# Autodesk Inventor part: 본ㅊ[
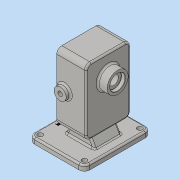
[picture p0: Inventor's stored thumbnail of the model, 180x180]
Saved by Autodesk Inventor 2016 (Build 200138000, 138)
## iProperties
Created: 2020-04
Part Number: 본ㅊ[
Material: 일반
Document SubType Name: Modeling
Designer: Administrator
Density: 1 g/cm^3
Appearance: 기본값
Author: Administrator
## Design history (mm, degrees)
sketch "스케치1"
  geometry: L1 (50, 60)-(-50, 60); L2 (-50, 60)-(-50, -60); L3 (-50, -60)-(50, -60); L4 (50, -60)-(50, 60); L5 (50, 60)-(-50, -60); L6 (-50, 60)-(50, -60); 1 further point
  constraints: 12 end point, 2 midpoint, 2 parallel, 1 horizontal, 1 perpendicular
  dimensions: "d0" = 100 distance of L3.end L2.end; "d1" = 120 distance of L2.end L1.end
extrude "돌출1" new body sketch "스케치1" distance "d2" = 10; taper "d3" = 0 deg
fillet "모깎기1" dims "d4" = 10
fillet "모깎기2" dims "d5" = 3
node "작업 평면1"
sketch "스케치2"
  geometry: L1 (90, 0)-(73, 0); L2 (0, 0)-(80, 0) reference; 1 further point
  constraints: 2 end point, 1 point on line
  dimensions: "d7" = 17 distance of L1.start L1.end
node "작업 평면2"
sketch "스케치3"
  geometry: L1 (0, -60)-(90, -60); L2 (150, -20)-(30, -20); L3 (30, -20)-(30, -100); L4 (30, -100)-(150, -100); L5 (150, -100)-(150, -20); L6 (150, -20)-(30, -100); L7 (30, -20)-(150, -100)
  constraints: 14 end point, 2 horizontal, 2 midpoint, 2 parallel, 1 perpendicular
  dimensions: "d8" = 90 distance of L1.start L1.end; "d9" = 120 distance of L4.end L3.end; "d10" = 80 distance of L3.end L2.end
extrude "돌출2" join sketch "스케치3" distance "d11" = 53; taper "d12" = 0 deg
fillet "모깎기3" dims "d13" = 9
fillet "모깎기4" dims "d14" = 9
sketch "스케치4"
  geometry: L1 (-36, 112)-(-36, 68); L2 (-84, 112)-(-84, 68); A1 r 24 centre (-60, 112) between (-36, 112) and (-84, 112); A2 r 24 centre (-60, 68) between (-84, 68) and (-36, 68); 1 further point
  constraints: 4 end point, 4 point on circle, 2 centre point, 2 tangent, 1 vertical
extrude "돌출3" cut sketch "스케치4" distance "d20" = 29; taper "d21" = 0 deg
sketch "스케치5"
  geometry: C1 r 12.5 at (-60, 112); C2 r 12.5 at (-60, 68); A1 r 24 centre (-60, 112) between (-36, 112) and (-84, 112) reference; A2 r 24 centre (-60, 68) between (-84, 68) and (-36, 68) reference; 1 further point
  constraints: 2 centre point, 2 coincident
  dimensions: "d22" = 25 diameter of C1; "d23" = 25 diameter of C2
extrude "돌출4" cut sketch "스케치5" distance "d24" = 15; taper "d25" = 0 deg
sketch "스케치6"
  geometry: C1 r 12.5 at (60, 112) reference; C2 r 19 at (60, 112); 1 further point
  constraints: 1 centre point, 1 coincident
  dimensions: "d26" = 38 diameter of C2
extrude "돌출5" join sketch "스케치6" distance "d27" = 17; taper "d28" = 0 deg
sketch "스케치7"
  geometry: C1 r 8.5 at (0, 0); 1 further point
  constraints: 1 centre point
  dimensions: "d29" = 17 diameter of C1
extrude "돌출6" cut sketch "스케치7" stored distance "d30" = 17; taper "d31" = 0 deg
fillet "모깎기5" dims "d32" = 3
fillet "모깎기6" dims "d33" = 3
sketch "스케치8"
  geometry: C1 r 14 at (0, 0); 1 further point
  constraints: 1 centre point
  dimensions: "d34" = 28 diameter of C1
extrude "돌출7" cut sketch "스케치8" distance "d35" = 7.3; taper "d36" = 0 deg
chamfer "모따기1" distance "d37" = 0.7; stored, may be unused: second distance "d38" = 2, angle "d39" = 30 deg
feature "분할1"
fillet "모깎기7" dims "d40" = 0.5
chamfer "모따기2" distance "d41" = 1; stored, may be unused: second distance "d42" = 2, angle "d43" = 30 deg
feature "분할2"
sketch "스케치9"
  geometry: L1 (0, 29)-(0, 73) reference; L2 (0, 51)-(-14, 51); C1 r 11 at (-14, 51); 1 further point
  constraints: 2 end point, 1 centre point, 1 coincident, 1 horizontal, 1 midpoint
  dimensions: "d45" = 14 distance of L2.start L2.end; "d46" = 22 diameter of C1
extrude "돌출8" join sketch "스케치9" distance "d47" = 8; taper "d48" = 0 deg
fillet "모깎기8" dims "d49" = 3
hole "구멍1" diameter "d52" = 8.376; stored, may be unused: countersink angle "d56" = 90 deg, drill point angle "d58" = 118 deg; dims "d50" = 10, "d51" = 10, "d53" = 20, "d54" = 4, "d55" = 2, "d57" = 27.3
sketch "스케치10"
  geometry: L1 (-47, 0)-(47, 0) reference; L2 (47, 0)-(47, 50) reference; L3 (-40, 57)-(40, 57) reference; L4 (-47, 0)-(-47, 50) reference; A1 r 7 centre (40, 50) between (47, 50) and (40, 57) reference; A2 r 7 centre (-40, 50) between (-40, 57) and (-47, 50) reference; 1 further point
hole "구멍2" sketch "스케치10" at (40, 50), (-40, 50) diameter "d59" = 9; stored, may be unused: countersink angle "d63" = 90 deg, drill point angle "d65" = 118 deg; dims "d60" = 20, "d61" = 4, "d62" = 2, "d64" = 27.3
sketch "스케치11"
  geometry: L1 (50, -50)-(50, 50) reference; L2 (50, 0)-(33, 0); L3 (33, 0)-(6.5, 0); L4 (-20, -24)-(33, -24); L5 (33, -24)-(33, 24); L6 (33, 24)-(-20, 24); L7 (-20, 24)-(-20, -24); L8 (-20, -24)-(33, 24); L9 (33, -24)-(-20, 24); 1 further point
  constraints: 16 end point, 3 horizontal, 3 midpoint, 2 parallel, 1 perpendicular
  dimensions: "d66" = 17 distance of L2.start L2.end; "d68" = 26.5 distance of L2.end L3.end; "d69" = 53 distance of L6.end L5.end; "d70" = 48 distance of L5.end L4.end
extrude "돌출9" join sketch "스케치11" stored distance "d71" = 8; taper "d72" = -30 deg
feature "면 기울기1" dims angle "d73" = -30 deg
feature "면 기울기2" dims angle "d74" = -30 deg
fillet "모깎기9" dims "d75" = 3
fillet "모깎기10" dims "d76" = 3
sketch "스케치12"
  geometry: L1 (-29, 147)-(-91, 147) reference; L2 (-29, 150)-(-91, 150) reference; L3 (-100, 141)-(-100, 90) reference; L4 (-100, 90)-(-100, 39) reference; L5 (-29, 30)-(-91, 30) reference; L6 (-20, 90)-(-20, 39) reference; L7 (-20, 141)-(-20, 90) reference; L8 (-36, 68)-(-36, 112) reference; L9 (-84, 68)-(-84, 112) reference; A1 r 9 centre (-91, 141) between (-91, 150) and (-100, 141) reference; A2 r 9 centre (-91, 39) between (-100, 39) and (-91, 30) reference; A3 r 9 centre (-29, 39) between (-29, 30) and (-20, 39) reference; A4 r 9 centre (-29, 141) between (-20, 141) and (-29, 150) reference; A5 r 24 centre (-60, 112) between (-36, 112) and (-84, 112) reference; A6 r 24 centre (-60, 68) between (-84, 68) and (-36, 68) reference; 1 further point
hole "구멍3" sketch "스케치12" at (-91, 141) diameter "d77" = 4.134; stored, may be unused: countersink angle "d81" = 90 deg, drill point angle "d83" = 118 deg; dims "d78" = 10, "d79" = 4, "d80" = 2, "d82" = 12
sketch "스케치13"
  geometry: L1 (-29, 150)-(-91, 150) reference; L2 (-100, 141)-(-100, 90) reference; L3 (-100, 90)-(-100, 39) reference; L4 (-29, 30)-(-91, 30) reference; L5 (-20, 90)-(-20, 39) reference; L6 (-20, 141)-(-20, 90) reference; L7 (-36, 68)-(-36, 112) reference; L8 (-84, 68)-(-84, 112) reference; C1 r 2.067 at (-29, 112) reference; C2 r 2.067 at (-91, 112) reference; C3 r 2.067 at (-29, 141) reference; C4 r 2.067 at (-91, 141) reference; A1 r 9 centre (-91, 141) between (-91, 150) and (-100, 141) reference; A2 r 9 centre (-91, 39) between (-100, 39) and (-91, 30) reference; A3 r 9 centre (-29, 39) between (-29, 30) and (-20, 39) reference; A4 r 9 centre (-29, 141) between (-20, 141) and (-29, 150) reference; A5 r 24 centre (-60, 112) between (-36, 112) and (-84, 112) reference; A6 r 24 centre (-60, 68) between (-84, 68) and (-36, 68) reference; 1 further point
hole "구멍4" sketch "스케치13" at (-91, 39), (-29, 39) diameter "d90" = 4.134; stored, may be unused: countersink angle "d94" = 90 deg, drill point angle "d96" = 118 deg; dims "d91" = 10, "d92" = 4, "d93" = 2, "d95" = 12
sketch "스케치14"
  geometry: L1 (-50, -50)-(-50, 50) reference; L2 (40, -60)-(-40, -60) reference; L3 (40, 60)-(-40, 60) reference; 2 further points
  constraints: 1 other
  dimensions: "d100" = 10 distance from line of L1 point (-40, 0); "d104" = 60 distance from line of L3 point (-40, 0)
feature "엠보싱1" sketch "스케치14" dims "d102" = 0.5, "d103" = 0
feature "분할3"
node "솔리드1"
mirror "대칭1"
mirror "대칭2"
pattern_linear "직사각형 패턴1" dims "d86" = 62
pattern_linear "직사각형 패턴2" dims "d89" = 29
pattern_linear "직사각형 패턴3" dims "d99" = 29
node "투영된 루프1"
node "투영된 루프2"
node "투영된 루프3"
other parameters: "d6" = 0
